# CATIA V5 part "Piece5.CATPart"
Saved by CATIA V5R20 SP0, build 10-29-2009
Part number: Piece5
Bounding box of the stored display mesh (mm): x 0 to 100, y 259.019 to 301.034, z -135.197 to 111.247
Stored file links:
  C:\Users\Lambert\Desktop\IAO\Piece5.CATPart
  C:\Users\Lambert\Desktop\IAO\Produit1.CATProduct
  C:\Users\Lambert\Desktop\IAO\skl_general.CATPart
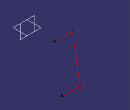
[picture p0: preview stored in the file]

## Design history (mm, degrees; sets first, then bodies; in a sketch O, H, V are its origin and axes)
Set1
  Line1 "Bielle 5": type PtPt, FirstPoint DatumPoint1, SecondPoint DatumPoint2, Support Plane1
  Line2 "Axe_pivot_50": type Normal, RefPoint DatumPoint1, RefSkin Plane1, Start 0, End 100
  Line3 "Axe_pivot_52": type Normal, RefPoint DatumPoint2, RefSkin Plane1, Start 0, End 100
Set2
  DatumPoint1 "D": linked copy from another document
  Plane1 "Plan_Ref": linked copy from another document
  DatumPoint2 "C": linked copy from another document
Body1 (main body)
